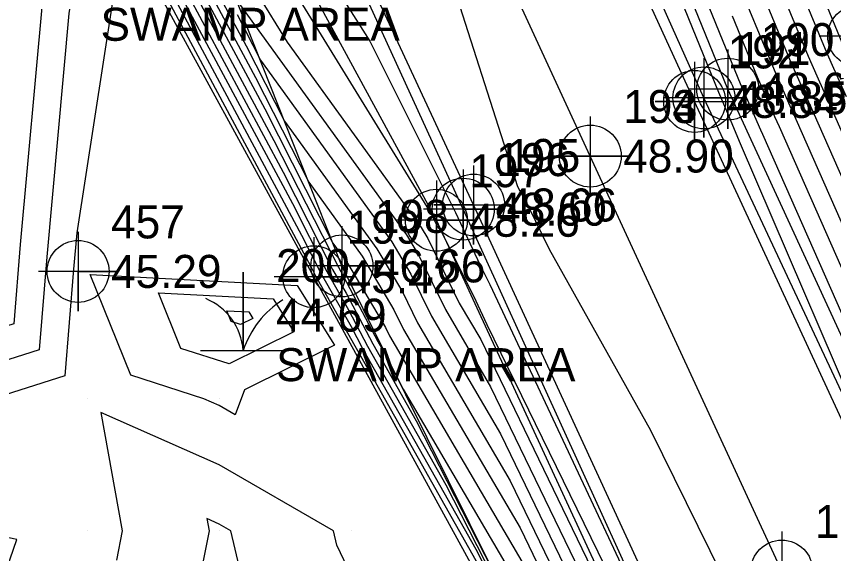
# Model space of a CAD drawing. Extents: x 2090860 to 2091277, y 159470 to 160080.
# Drawn here: x 2091044.6 to 2091106.5, y 159678.3 to 159719 of the extents above; entities that cross this region are included whole.
import ezdxf

# ---------------------------------------------------------------- set-up
doc = ezdxf.new("R2010")
doc.units = 0
for name, color, linetype in [('DTM Contours Major', 7, 'Continuous'), ('DTM Contours Minor', 7, 'Continuous'), ('Exist DTM Breakline', 7, 'Continuous'), ('Exist DTM Breakline Cogo Elevation', 7, 'Continuous'), ('Exist DTM Breakline Cogo Number', 7, 'Continuous'), ('Exist DTM Breakline Cogo Point CELL', 7, 'Continuous'), ('Exist DTM Crownline', 7, 'Continuous'), ('Exist DTM Crownline Cogo Elevation', 7, 'Continuous'), ('Exist DTM Crownline Cogo Number', 7, 'Continuous'), ('Exist DTM Crownline Cogo Point CELL', 7, 'Continuous'), ('Exist DTM QL2 LIDAR Elevation Point', 7, 'Continuous'), ('Exist DTM Regular Point CELL', 7, 'Continuous'), ('Exist DTM Regular Point Cogo Elevation', 7, 'Continuous'), ('Exist DTM Regular Point Cogo Number', 7, 'Continuous'), ('Exist Hydro Swamp or Marsh', 7, 'Continuous'), ('Exist Hydro Swamp or Marsh Cogo Comment', 7, 'Continuous'), ('Exist Hydro Swamp or Marsh Cogo Elevation', 7, 'Continuous'), ('Exist Hydro Swamp or Marsh Cogo Number', 7, 'Continuous'), ('Exist Roads EOP', 7, 'Continuous'), ('Exist Roads EOP Cogo Elevation', 7, 'Continuous'), ('Exist Roads EOP Cogo Number', 7, 'Continuous'), ('Exist Roads EOP Cogo Point CELL', 7, 'Continuous'), ('Exist Roads EOT', 7, 'Continuous'), ('Exist Roads EOT Cogo Elevation', 7, 'Continuous'), ('Exist Roads EOT Cogo Number', 7, 'Continuous'), ('Exist Roads EOT Cogo Point CELL', 7, 'Continuous')]:
    doc.layers.add(name, color=color, linetype=linetype)

msp = doc.modelspace()

# ---------------------------------------------------------------- linework, layer by layer
at = {"layer": 'DTM Contours Major'}
for points in [[(2091099.154, 159783.181), (2091099.586, 159776.685), (2091095.347, 159760.92), (2091094.892, 159756.071), (2091093.367, 159756.873), (2091092.489, 159757.381), (2091091.65, 159757.144), (2091080.908, 159760.58), (2091079.033, 159758.835), (2091075.343, 159753.965), (2091056.615, 159737.315), (2091055.277, 159735.743), (2091054.293, 159734.446), (2091049.816, 159730.618), (2091048.96, 159722.933), (2091049.119, 159722.392), (2091048.623, 159719.182), (2091046.944, 159700.747), (2091046.379, 159693.703), (2091023.075, 159686.293)], [(2091109.918, 159718.472), (2091105.9, 159728.566), (2091101.492, 159739.908), (2091098.461, 159748.511), (2091097.821, 159750.345), (2091097.24, 159750.65), (2091089.505, 159755.131), (2091088.96, 159754.976), (2091084.801, 159753.611), (2091084.572, 159753.055), (2091082.494, 159751.437), (2091077.793, 159749.325), (2091058.398, 159735.631), (2091057.424, 159734.927), (2091055.456, 159731.425), (2091054.477, 159730.468), (2091054.63, 159729.231), (2091055.24, 159724.01), (2091065.545, 159704.781), (2091068.165, 159699.625), (2091069.803, 159696.726), (2091071.248, 159693.989), (2091077.176, 159683.472), (2091085.357, 159667.475)], [(2091107.198, 159716.962), (2091099.863, 159734.767)], [(2091060.663, 159724.288), (2091065.155, 159716.997), (2091075.303, 159702.961), (2091075.794, 159702.131), (2091078.188, 159697.249), (2091079.813, 159694.479), (2091091.479, 159670.351)], [(2091057.906, 159723.38), (2091062.756, 159714.33), (2091066.788, 159706.396), (2091070.834, 159700.8), (2091073.238, 159696.743), (2091073.968, 159695.254), (2091082.79, 159680.214), (2091088.287, 159668.846)], [(2091111.915, 159692.566), (2091103.71, 159711.156), (2091103.155, 159712.384), (2091102.055, 159714.877), (2091099.068, 159722.128)], [(2091060.757, 159692.637), (2091057.108, 159693.807), (2091055.402, 159698.029), (2091064.088, 159697.567), (2091065.649, 159695.073), (2091060.757, 159692.637)]]:
    msp.add_lwpolyline(points, dxfattribs=at)
at = {"layer": 'DTM Contours Minor'}
for points in [[(2091096.241, 159783.219), (2091096.632, 159777.335), (2091091.681, 159758.923), (2091079.716, 159762.75), (2091078.018, 159761.17), (2091073.023, 159754.576), (2091055.937, 159739.388), (2091053.43, 159736.44), (2091051.585, 159734.01), (2091047.854, 159730.819), (2091047.036, 159723.479), (2091046.615, 159720.238), (2091044.926, 159701.687), (2091044.444, 159695.681), (2091024.575, 159689.363), (2091020.749, 159697.899), (2091025.515, 159711.112), (2091026.673, 159719.509), (2091028.491, 159726.914), (2091025.301, 159727.962), (2091021.891, 159724.475), (2091014.39, 159716.435), (2090995.777, 159702.98), (2090992.609, 159700.254)], [(2091102.068, 159783.144), (2091102.54, 159776.034), (2091100.183, 159767.269), (2091098.84, 159752.951), (2091094.335, 159755.317), (2091091.743, 159756.818), (2091089.266, 159756.117), (2091082.1, 159758.41), (2091080.048, 159756.5), (2091077.664, 159753.353), (2091057.292, 159735.243), (2091057.124, 159735.045), (2091057, 159734.882), (2091051.778, 159730.417), (2091051.468, 159727.633), (2091052.528, 159724.019), (2091049.213, 159702.565), (2091048.962, 159699.806), (2091048.314, 159691.724), (2091021.574, 159683.222)], [(2091110.18, 159720.929), (2091102.507, 159740.673), (2091102.076, 159741.898), (2091098.523, 159752.07), (2091095.303, 159753.762), (2091090.997, 159756.256), (2091086.882, 159755.091), (2091083.292, 159756.24), (2091081.063, 159754.166), (2091079.984, 159752.742), (2091069.862, 159743.743), (2091057.692, 159735.151), (2091057.4, 159734.94), (2091056.81, 159733.89), (2091053.174, 159730.332), (2091053.742, 159725.736), (2091053.907, 159724.325), (2091066.94, 159700.006), (2091067.301, 159699.295), (2091070.185, 159694.19), (2091070.474, 159693.642), (2091081.681, 159673.757)], [(2091108.04, 159724.748), (2091102, 159740.29), (2091100.269, 159745.204), (2091098.172, 159751.208), (2091096.272, 159752.206), (2091090.251, 159755.693), (2091084.499, 159754.065), (2091084.484, 159754.07), (2091084.431, 159754.02), (2091081.99, 159752.118), (2091081.294, 159751.805), (2091058.045, 159735.391), (2091057.412, 159734.933), (2091056.133, 159732.658), (2091053.826, 159730.4), (2091054.186, 159727.483), (2091054.574, 159724.168), (2091066.243, 159702.393), (2091067.733, 159699.46), (2091069.994, 159695.458), (2091070.861, 159693.815), (2091079.429, 159678.614), (2091085.16, 159667.407)], [(2091109.431, 159718.14), (2091103.76, 159732.384), (2091100.985, 159739.525), (2091098.275, 159747.218), (2091097.012, 159749.764), (2091089.63, 159754.028), (2091089.296, 159754.532), (2091085.115, 159753.16), (2091084.654, 159752.045), (2091082.998, 159750.755), (2091074.292, 159746.844), (2091058.751, 159735.872), (2091057.436, 159734.921), (2091055.026, 159730.634), (2091055.037, 159730.627), (2091055.054, 159730.62), (2091055.163, 159730.22), (2091055.907, 159723.852), (2091064.848, 159707.168), (2091068.598, 159699.79), (2091069.612, 159697.994), (2091071.635, 159694.163), (2091074.923, 159688.329), (2091081.29, 159675.881)], [(2091107.547, 159719.758), (2091100.062, 159737.927), (2091099.686, 159738.852), (2091099.347, 159739.624), (2091094.676, 159749.044), (2091090.082, 159751.698), (2091089.004, 159753.327), (2091085.742, 159752.256), (2091084.82, 159750.026), (2091084.007, 159749.393), (2091067.289, 159741.882), (2091059.458, 159736.353), (2091057.459, 159734.908), (2091055.552, 159731.515), (2091055.643, 159731.449), (2091055.791, 159731.394), (2091056.723, 159727.962), (2091057.24, 159723.537), (2091063.453, 159711.942), (2091068.62, 159701.777), (2091069.717, 159700.26), (2091072.599, 159695.395), (2091072.913, 159694.755), (2091083.535, 159676.648)], [(2091113.443, 159677.236), (2091111.307, 159681.76), (2091110.309, 159684.106), (2091099.498, 159709.302), (2091098.524, 159711.61), (2091097.844, 159713.197), (2091091.534, 159728.707), (2091087.955, 159732.339), (2091087.995, 159731.685), (2091087.449, 159731.209), (2091080.082, 159737.993), (2091077.854, 159740.578), (2091075.81, 159742.572), (2091073.211, 159741.431)], [(2091073.211, 159741.431), (2091072.6, 159741.155), (2091064.004, 159737.095), (2091063.512, 159736.868), (2091061.91, 159736.267), (2091064.634, 159732.695), (2091065.877, 159731.578), (2091066.228, 159731.026), (2091066.842, 159729.798), (2091069.45, 159725.322), (2091070.914, 159722.651), (2091076.971, 159723.674), (2091082.588, 159706.063), (2091083.467, 159704.482), (2091085.006, 159701.325), (2091092.675, 159687.628), (2091098.961, 159674.873)], [(2091112.705, 159683.887), (2091101.171, 159710.019), (2091101.027, 159710.337), (2091099.483, 159713.835), (2091098.67, 159715.809), (2091089.511, 159738.318)], [(2091107.52, 159712.862), (2091106.348, 159715.454), (2091105.912, 159716.44), (2091099.664, 159731.607)], [(2091063.021, 159730.282), (2091071.412, 159717.076), (2091077.897, 159704.113), (2091079.756, 159700.155), (2091080.51, 159698.642), (2091091.966, 159674.206)], [(2091111.126, 159701.246), (2091106.25, 159712.293), (2091105.284, 159714.431), (2091104.627, 159715.919), (2091099.466, 159728.448)], [(2091061.536, 159727.595), (2091076.143, 159703.883), (2091076.42, 159703.501), (2091076.433, 159703.478), (2091077.055, 159702.211), (2091079.262, 159697.783), (2091080.273, 159695.626), (2091092.352, 159670.911)], [(2091111.521, 159696.906), (2091104.98, 159711.725), (2091104.22, 159713.407), (2091103.341, 159715.398), (2091099.267, 159725.288)], [(2091056.573, 159723.695), (2091064.15, 159709.555), (2091069.03, 159699.955), (2091069.421, 159699.263), (2091072.022, 159694.337), (2091072.671, 159693.186), (2091073.926, 159690.732), (2091084.279, 159673.082)], [(2091058.572, 159723.222), (2091062.058, 159716.717), (2091064.957, 159711.014), (2091071.951, 159701.34), (2091073.877, 159698.09), (2091075.023, 159695.753), (2091082.046, 159683.781), (2091089.085, 159669.222)], [(2091061.294, 159720.251), (2091074.185, 159702.421), (2091075.155, 159700.784), (2091077.133, 159696.75), (2091080.558, 159690.913), (2091090.681, 159669.974)], [(2091061.361, 159719.104), (2091063.126, 159715.633), (2091073.068, 159701.88), (2091074.516, 159699.437), (2091076.078, 159696.252), (2091081.302, 159687.347), (2091089.883, 159669.598)], [(2091112.31, 159688.227), (2091102.441, 159710.588), (2091102.091, 159711.36), (2091100.769, 159714.356), (2091098.869, 159718.968)], [(2091050.228, 159699.4), (2091065.918, 159698.564), (2091068.739, 159694.06), (2091061.923, 159690.665), (2091061.22, 159688.78), (2091060, 159689.485), (2091058.836, 159690), (2091053.31, 159691.773), (2091050.228, 159699.4)], [(2091061.613, 159695.615), (2091060.906, 159695.842), (2091060.576, 159696.659), (2091062.257, 159696.569), (2091062.56, 159696.087), (2091061.613, 159695.615)], [(2091070, 159676.646), (2091068.908, 159678.908), (2091068.649, 159680), (2091060, 159684.999), (2091051.033, 159688.967), (2091052.659, 159680), (2091052.215, 159677.785)], [(2091042.178, 159672.178), (2091044.668, 159679.336), (2091028.311, 159682.77)], [(2091070.535, 159660.264), (2091070, 159664.078), (2091063.899, 159670), (2091062.629, 159672.629), (2091060.888, 159680), (2091060, 159680.513), (2091059.079, 159680.921), (2091059.246, 159680), (2091057.702, 159672.298), (2091056.213, 159670), (2091054.811, 159665.189), (2091054.242, 159660), (2091060, 159650.781), (2091063.085, 159656.915), (2091070, 159657.864), (2091070.622, 159660.118), (2091070.535, 159660.264)]]:
    msp.add_lwpolyline(points, dxfattribs=at)
at = {"layer": 'Exist DTM Breakline'}
for points in [[(2091196.63, 159502.872), (2091177.33, 159544.144), (2091161.139, 159578.46), (2091145.393, 159612.39), (2091128.083, 159650.689), (2091112.842, 159682.377), (2091098.521, 159713.445), (2091088.424, 159738.261), (2091087.489, 159747.73)], [(2091169.184, 159489.682), (2091149.135, 159531.027), (2091132.914, 159565.727), (2091117.093, 159597.885), (2091099.249, 159637.73), (2091085.443, 159667.505), (2091069.301, 159700.059), (2091060.276, 159722.819), (2091058.458, 159734.195), (2091059.361, 159735), (2091060.617, 159735.809)], [(2091168.326, 159489.347), (2091148.612, 159530.829), (2091132.315, 159565.389), (2091116.339, 159597.574), (2091098.698, 159637.587), (2091084.7, 159667.248), (2091067.163, 159699.242), (2091053.414, 159724.442), (2091052.893, 159730.303), (2091057.39, 159734.945)], [(2091175.557, 159492.591), (2091156.216, 159533.598), (2091139.639, 159569.307), (2091124.335, 159601.659), (2091105.938, 159640.92), (2091091.734, 159670.471), (2091076.451, 159703.516), (2091059.361, 159735)]]:
    msp.add_lwpolyline(points, dxfattribs=at)
at = {"layer": 'Exist DTM Breakline Cogo Point CELL'}
for points in [[(2091108.438, 159720.464), (2091108.438, 159714.464), (2091108.438, 159717.464), (2091111.438, 159717.464), (2091105.438, 159717.464)], [(2091098.521, 159716.445), (2091098.521, 159710.445), (2091098.521, 159713.445), (2091101.521, 159713.445), (2091095.521, 159713.445)], [(2091076.451, 159706.516), (2091076.451, 159700.516), (2091076.451, 159703.516), (2091079.451, 159703.516), (2091073.451, 159703.516)], [(2091069.301, 159703.059), (2091069.301, 159697.059), (2091069.301, 159700.059), (2091072.301, 159700.059), (2091066.301, 159700.059)], [(2091067.163, 159702.242), (2091067.163, 159696.242), (2091067.163, 159699.242), (2091070.163, 159699.242), (2091064.163, 159699.242)]]:
    msp.add_lwpolyline(points, dxfattribs=at)
for centre in [(2091108.438, 159717.464), (2091098.521, 159713.445), (2091076.451, 159703.516), (2091069.301, 159700.059), (2091067.163, 159699.242)]:
    msp.add_circle(centre, 2.344, dxfattribs=at)
at = {"layer": 'Exist DTM Crownline'}
msp.add_lwpolyline([(2091186.231, 159497.374), (2091150.267, 159573.786), (2091135.077, 159606.786), (2091117.269, 159645.439), (2091102.614, 159676.949), (2091088.105, 159708.377), (2091072.916, 159741.265)], dxfattribs=at)
at = {"layer": 'Exist DTM Crownline Cogo Point CELL'}
for points in [[(2091088.105, 159711.377), (2091088.105, 159705.377), (2091088.105, 159708.377), (2091091.105, 159708.377), (2091085.105, 159708.377)], [(2091102.614, 159679.949), (2091102.614, 159673.949), (2091102.614, 159676.949), (2091105.614, 159676.949), (2091099.614, 159676.949)]]:
    msp.add_lwpolyline(points, dxfattribs=at)
for centre in [(2091088.105, 159708.377), (2091102.614, 159676.949)]:
    msp.add_circle(centre, 2.344, dxfattribs=at)
at = {"layer": 'Exist DTM QL2 LIDAR Elevation Point'}
for p, q in [((2091050, 159690), (2091050, 159690)), ((2091060, 159690), (2091060, 159690)), ((2091050, 159680), (2091050, 159680)), ((2091060, 159680), (2091060, 159680)), ((2091070, 159680), (2091070, 159680))]:
    msp.add_line(p, q, dxfattribs=at)
at = {"layer": 'Exist DTM Regular Point CELL'}
msp.add_lwpolyline([(2091049.317, 159702.641), (2091049.317, 159696.641), (2091049.317, 159699.641), (2091052.317, 159699.641), (2091046.317, 159699.641)], dxfattribs=at)
msp.add_circle((2091049.317, 159699.641), 2.344, dxfattribs=at)
at = {"layer": 'Exist Hydro Swamp or Marsh'}
msp.add_line((2091061.818, 159696.33), (2091061.818, 159696.33), dxfattribs=at)
msp.add_lwpolyline([(2091058.593, 159693.656), (2091061.819, 159693.656), (2091061.819, 159699.573), (2091061.819, 159693.656), (2091065.044, 159693.656)], dxfattribs=at)
for centre, radius, start, end in [((2091057.219, 159693.323), 4.612, 4.14034, 67.53497), ((2091068.66, 159691.383), 7.208, 122.12745, 161.62219)]:
    msp.add_arc(centre, radius, start, end, dxfattribs=at)
at = {"layer": 'Exist Roads EOP'}
for points in [[(2091195.022, 159502.3), (2091175.816, 159543.301), (2091159.602, 159577.847), (2091143.942, 159611.542), (2091126.198, 159649.797), (2091111.241, 159681.734), (2091096.716, 159712.783), (2091082.116, 159745.373)], [(2091176.987, 159492.996), (2091157.634, 159534.321), (2091140.802, 159570.232), (2091125.679, 159602.447), (2091107.654, 159641.501), (2091093.369, 159671.636), (2091078.486, 159704.356), (2091063.606, 159736.869)]]:
    msp.add_lwpolyline(points, dxfattribs=at)
at = {"layer": 'Exist Roads EOP Cogo Point CELL'}
for points in [[(2091096.716, 159715.783), (2091096.716, 159709.783), (2091096.716, 159712.783), (2091099.716, 159712.783), (2091093.716, 159712.783)], [(2091078.486, 159707.356), (2091078.486, 159701.356), (2091078.486, 159704.356), (2091081.486, 159704.356), (2091075.486, 159704.356)]]:
    msp.add_lwpolyline(points, dxfattribs=at)
for centre in [(2091096.716, 159712.783), (2091078.486, 159704.356)]:
    msp.add_circle(centre, 2.344, dxfattribs=at)
at = {"layer": 'Exist Roads EOT'}
for points in [[(2091194.37, 159502.018), (2091175.119, 159542.803), (2091158.987, 159577.703), (2091143.368, 159611.224), (2091125.349, 159649.375), (2091110.434, 159681.3), (2091096.012, 159712.514), (2091081.141, 159744.981)], [(2091158.031, 159534.505), (2091141.446, 159570.27), (2091126.357, 159602.867), (2091108.385, 159641.68), (2091094.245, 159672.193), (2091079.271, 159704.671), (2091064.194, 159737.108)]]:
    msp.add_lwpolyline(points, dxfattribs=at)
at = {"layer": 'Exist Roads EOT Cogo Point CELL'}
for points in [[(2091096.012, 159715.514), (2091096.012, 159709.514), (2091096.012, 159712.514), (2091093.012, 159712.514), (2091099.012, 159712.514)], [(2091088.105, 159711.377), (2091088.105, 159705.377), (2091088.105, 159708.377), (2091085.105, 159708.377), (2091091.105, 159708.377)], [(2091079.271, 159707.671), (2091079.271, 159701.671), (2091079.271, 159704.671), (2091076.271, 159704.671), (2091082.271, 159704.671)], [(2091102.614, 159679.949), (2091102.614, 159673.949), (2091102.614, 159676.949), (2091099.614, 159676.949), (2091105.614, 159676.949)]]:
    msp.add_lwpolyline(points, dxfattribs=at)
for centre in [(2091096.012, 159712.514), (2091088.105, 159708.377), (2091079.271, 159704.671), (2091102.614, 159676.949)]:
    msp.add_circle(centre, 2.344, dxfattribs=at)

# ---------------------------------------------------------------- texts
at = {"layer": 'Exist DTM Breakline Cogo Elevation'}
for s, p in [('48.69', (2091101.021, 159712.195)), ('48.26', (2091078.951, 159702.266)), ('46.66', (2091071.801, 159698.809)), ('45.42', (2091069.663, 159697.992))]:
    msp.add_text(s, height=2.5, dxfattribs=at).set_placement(p)
at = {"layer": 'Exist DTM Breakline Cogo Number'}
for s, p in [('190', (2091101.021, 159715.945)), ('197', (2091078.951, 159706.016)), ('198', (2091071.801, 159702.559)), ('199', (2091069.663, 159701.742))]:
    msp.add_text(s, height=2.5, dxfattribs=at).set_placement(p)
at = {"layer": 'Exist DTM Crownline Cogo Elevation'}
msp.add_text('48.90', height=2.5, dxfattribs=at).set_placement((2091090.605, 159707.127))
at = {"layer": 'Exist DTM Crownline Cogo Number'}
for s, p in [('194', (2091090.605, 159710.877)), ('181', (2091105.114, 159679.449))]:
    msp.add_text(s, height=2.5, dxfattribs=at).set_placement(p)
at = {"layer": 'Exist DTM Regular Point Cogo Elevation'}
msp.add_text('45.29', height=2.5, dxfattribs=at).set_placement((2091051.817, 159698.391))
at = {"layer": 'Exist DTM Regular Point Cogo Number'}
msp.add_text('457', height=2.5, dxfattribs=at).set_placement((2091051.817, 159702.141))
at = {"layer": 'Exist Hydro Swamp or Marsh Cogo Comment'}
for p in [(2091051.019, 159717.106), (2091064.318, 159691.33)]:
    msp.add_text('SWAMP AREA', height=2.5, dxfattribs=at).set_placement(p)
at = {"layer": 'Exist Hydro Swamp or Marsh Cogo Elevation'}
msp.add_text('44.69', height=2.5, dxfattribs=at).set_placement((2091064.318, 159695.08))
at = {"layer": 'Exist Hydro Swamp or Marsh Cogo Number'}
msp.add_text('200', height=2.5, dxfattribs=at).set_placement((2091064.318, 159698.83))
at = {"layer": 'Exist Roads EOP Cogo Elevation'}
for s, p in [('48.85', (2091099.216, 159711.533)), ('48.60', (2091080.986, 159703.106))]:
    msp.add_text(s, height=2.5, dxfattribs=at).set_placement(p)
at = {"layer": 'Exist Roads EOP Cogo Number'}
for s, p in [('191', (2091099.216, 159715.283)), ('196', (2091080.986, 159706.856))]:
    msp.add_text(s, height=2.5, dxfattribs=at).set_placement(p)
at = {"layer": 'Exist Roads EOT Cogo Elevation'}
for s, p in [('48.84', (2091098.512, 159711.264)), ('48.90', (2091090.605, 159707.127)), ('48.66', (2091081.771, 159703.421))]:
    msp.add_text(s, height=2.5, dxfattribs=at).set_placement(p)
at = {"layer": 'Exist Roads EOT Cogo Number'}
for s, p in [('192', (2091098.512, 159715.014)), ('193', (2091090.605, 159710.877)), ('195', (2091081.771, 159707.171)), ('180', (2091105.114, 159679.449))]:
    msp.add_text(s, height=2.5, dxfattribs=at).set_placement(p)

doc.saveas('drawing.dxf')
